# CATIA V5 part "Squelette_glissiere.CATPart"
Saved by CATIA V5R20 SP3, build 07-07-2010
Part number: Squelette_glissiere
Publications: "Plan.1", "Point.1", "Droite.1", "Plan.2"
Bounding box of the stored display mesh (mm): x 0 to 0, y -14 to 6, z 0 to 0
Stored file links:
  C:\Documents and Settings\Propriétaire\Mes documents\IFMA\COURS\PROJ IAO\CATIA\Squelette_glissiere.CATPart
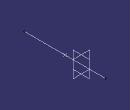
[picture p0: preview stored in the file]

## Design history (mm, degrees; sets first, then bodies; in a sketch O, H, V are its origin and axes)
Set1
  Plane1: type Offset, RefPlane zx-plane, Offset 0
  Point1: (0, -4, 0)
  Line1: type PtDir, RefPoint Point1, Direction Plane1, Start -10, End 10
  Plane2: type Offset, RefPlane yz-plane, Offset 0
Body1 (main body)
